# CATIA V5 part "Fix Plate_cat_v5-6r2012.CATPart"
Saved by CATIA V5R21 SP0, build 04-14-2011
Part number: Fix Plate
Bounding box of the stored display mesh (mm): x -45 to 45, y -150 to 150, z -40 to 230
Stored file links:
  D:\CATIA V5R21 E-RESOURCES\CATIA-V5R21\catia-v5r21-Tut\c16-catia-v5r21-tut\c16-catia-v5r21-tut05\Fix Plate_cat_v5r21.CATPart
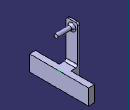
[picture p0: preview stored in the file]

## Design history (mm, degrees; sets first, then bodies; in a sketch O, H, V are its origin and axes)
Body1 (main body)
  Sketch1 on yz-plane, origin (0, 0, 0), H (0, 1, 0), V (0, 0, 1)
    line L1 (150, 40) -> (150, -40)
    line L2 (150, -40) -> (-150, -40)
    line L3 (-150, -40) -> (-150, 40)
    line L4 (-150, 40) -> (150, 40)
    length L4 = 300
    length L1 = 80
    vertical: L1 V, L3 V
    horizontal: L2 H, L4 H
    equidistance: L1 L3 O, L2 L4 O
  Pad1: profile Sketch1, direction (1, 0, 0), length 30
  Point1: type OnCurve, Support edge [face of Pad1 from Sketch1.L4 | end face of Pad1], Ratio 0.5
  Sketch2 on start face of Pad1, origin (0, 0, 0), H (0, -1, 0), V (0, 0, 1)
    circle A1 centre (0, 200) radius 10
    point P1 (0, 200)
    reference projected line E1 (-150, 40) -> (150, 40) from edge [start face of Pad1 | face of Pad1 from Sketch1.L4]
    radius A1 = 10
    distance E1 P1 = 160
    coincidence: P1 V
  Pad2: profile Sketch2, direction (1, 0, 0), length 45, mirrored extent
  Sketch3 on start face of Pad2, origin (-45, 0, 0), H (0, -1, 0), V (0, 0, 1)
    line L1 (30, -40) -> (-30, -40)
    line L2 (-30, -40) -> (-30, 230)
    line L3 (-30, 230) -> (30, 230)
    line L4 (30, 230) -> (30, -40)
    reference projected line E1 (-150, 40) -> (150, 40) from edge [start face of Pad1 | face of Pad1 from Sketch1.L4]
    length L3 = 60
    distance V L2 = 30
    distance E1 L3 = 190
    horizontal: L1 H, L3 H
    vertical: L2 V, L4 V
  Pad3: profile Sketch3, direction (1, 0, 0), length 10
  Sketch4 on end face of Pad3, origin (-35, 0, 0), H (0, 1, 0), V (0, 0, 1)
    line L1 (-30, 40) -> (30, 40)
    line L2 (30, 40) -> (30, -40)
    line L3 (30, -40) -> (-30, -40)
    line L4 (-30, -40) -> (-30, 40)
    reference projected line E1 (150, 40) -> (-150, 40) from edge [face of Pad1 from Sketch1.L4 | end face of Pad1]
    reference projected line E2 (-30, -40) -> (-30, 230) from edge [end face of Pad3 | face of Pad3 from Sketch3.L4]
    reference projected line E3 (-150, -40) -> (150, -40) from edge [face of Pad1 from Sketch1.L2 | end face of Pad1]
    reference projected line E4 (30, 230) -> (30, -40) from edge [end face of Pad3 | face of Pad3 from Sketch3.L2]
    horizontal: L1 H, L3 H
    vertical: L2 V, L4 V
    coincidence: L1 E1, L4 E2, L3 E3, L2 E4
  Pad4: profile Sketch4, direction (1, 0, 0), up to the existing solid (limit type 2)
  Fillet1: radius 10, on edge [face of Pad3 from Sketch3.L3 | face of Pad3]; edge [face of Pad2 from Sketch2.A1 | end face of Pad3]; edge [face of Pad4 | face of Pad3 from Sketch3.L3]; edge [end face of Pad3 | face of Pad1]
